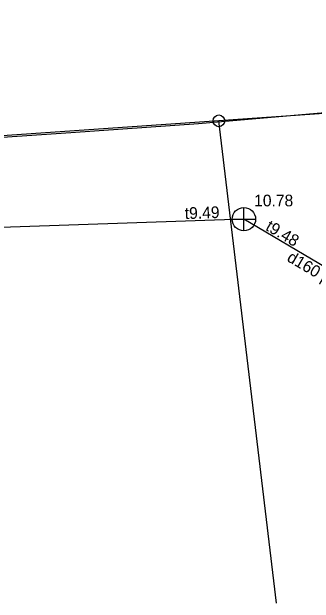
# Model space of a CAD drawing. Extents: x 502312.8 to 502402.4, y 308528.5 to 308602.
# Drawn here: x 502364.65 to 502377.59, y 308528.54 to 308553.83 of the extents above; entities that cross this region are included whole.
import ezdxf

# ---------------------------------------------------------------- set-up
doc = ezdxf.new("R2010")
doc.units = 0
for name, color, linetype in [('10', 7, 'Continuous'), ('24', 7, 'Continuous'), ('Level 51-1', 7, 'Continuous'), ('NORB_ZOGS_ZSTP_####_#', 7, 'Continuous'), ('SKAN_ELEM_####_####_#', 7, 'Continuous'), ('SKAN_ELEM_PAST_TKST_#', 7, 'Continuous'), ('SKAN_VADP_PAST_####_I', 7, 'Continuous'), ('SKAN_VADP_PAST_TKST_I', 7, 'Continuous'), ('TERT_KONT_####_####_#', 7, 'Continuous')]:
    doc.layers.add(name, color=color, linetype=linetype)

msp = doc.modelspace()

# ---------------------------------------------------------------- linework, layer by layer
at = {"layer": '10'}
msp.add_circle((502373.511, 308549.166), 0.25, dxfattribs=at)
at = {"layer": '24'}
for p, q in [((502381.693, 308549.732), (502373.511, 308549.166)), ((502373.511, 308549.166), (502339.503, 308546.814)), ((502375.986, 308528.536), (502373.511, 308549.166))]:
    msp.add_line(p, q, dxfattribs=at)
at = {"layer": 'Level 51-1'}
for p, q in [((502381.693, 308549.732), (502373.511, 308549.166)), ((502373.511, 308549.166), (502332.854, 308546.354))]:
    msp.add_line(p, q, dxfattribs=at)
at = {"layer": 'NORB_ZOGS_ZSTP_####_#'}
msp.add_line((502378.05, 308549.502), (502372.645, 308549.031), dxfattribs=at)
for points in [[(502372.645, 308549.031), (502367.18, 308548.658)], [(502367.18, 308548.658), (502339.57, 308546.773)]]:
    msp.add_lwpolyline(points, dxfattribs=at)
at = {"layer": 'SKAN_ELEM_####_####_#'}
for p, q in [((502374.583, 308544.459), (502374.583, 308545.459)), ((502374.083, 308544.959), (502375.083, 308544.959))]:
    msp.add_line(p, q, dxfattribs=at)
msp.add_circle((502374.583, 308544.959), 0.5, dxfattribs=at)
at = {"layer": 'SKAN_VADP_PAST_####_I'}
for points in [[(502374.583, 308544.959), (502345.837, 308543.972)], [(502381.626, 308540.804), (502374.583, 308544.959)]]:
    msp.add_lwpolyline(points, dxfattribs=at)
at = {"layer": 'TERT_KONT_####_####_#'}
msp.add_spline([(502368.421, 308580.073), (502364.888, 308583.145), (502359.074, 308582.726), (502336.999, 308579.84), (502335.385, 308579.318), (502336.097, 308569.387), (502336.741, 308557.487), (502335.314, 308546.766)], degree=3, dxfattribs=at)

# ---------------------------------------------------------------- texts
at = {"layer": 'SKAN_ELEM_PAST_TKST_#'}
msp.add_text('10.78', height=0.5, dxfattribs=at).set_placement((502375.022, 308545.509))
at = {"layer": 'SKAN_VADP_PAST_TKST_I'}
for s, rotation, p in [('t9.49', 1.9665, (502372.061, 308544.962)), ('t9.48', 329.4616, (502375.473, 308544.519)), ('d160 pl(pvh)', 329.5643, (502376.388, 308543.193))]:
    msp.add_text(s, height=0.5, rotation=rotation, dxfattribs=at).set_placement(p)

doc.saveas('drawing.dxf')
